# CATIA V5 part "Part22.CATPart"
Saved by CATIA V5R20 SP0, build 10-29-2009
Part number: VA 100812-4
Revision: ANY
Definition: UNKNOWN
Nomenclature: VA 100812-4
Source: Unknown
Bounding box of the stored display mesh (mm): x -3.012 to 3.012, y 0 to 5.3, z -2.75 to 2.75
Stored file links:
  C:\Users\Utente\Desktop\IO LAVORO\3D X SITO CF\CUMSA\3D files VA\VA 121012\Part22.CATPart
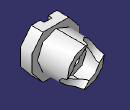
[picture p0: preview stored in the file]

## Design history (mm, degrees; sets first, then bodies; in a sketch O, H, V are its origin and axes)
Body1 "Cortar-Extruir4" (main body)
  Solid1: solid without history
